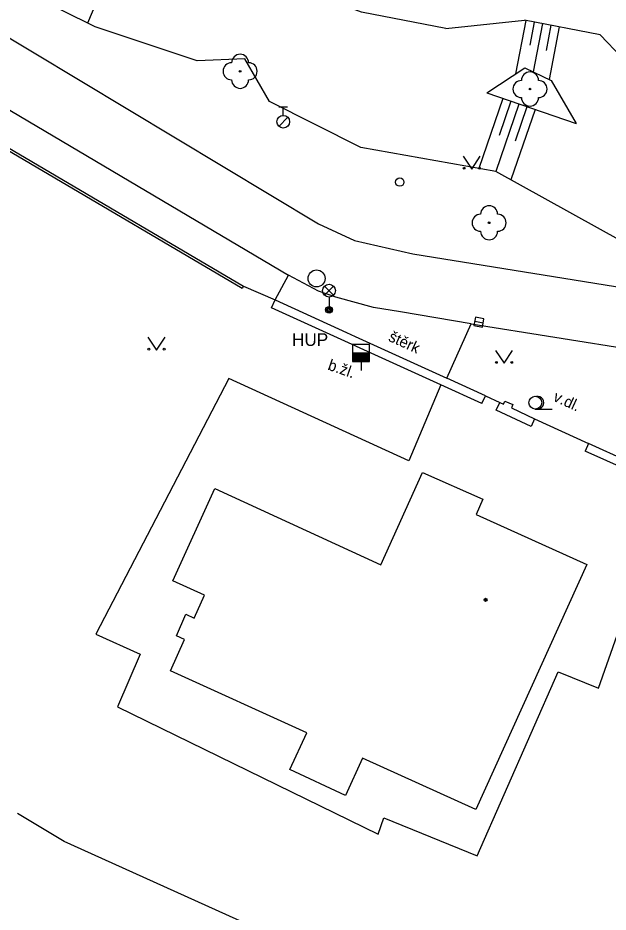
# Model space of a CAD drawing. Extents: x -600309 to -598967, y -1161267 to -1160292.
# Drawn here: x -600215.3 to -600180.6, y -1160958.5 to -1160906.1 of the extents above; entities that cross this region are included whole.
import ezdxf

# ---------------------------------------------------------------- set-up
doc = ezdxf.new("R2010")
doc.units = 0
for name, color, linetype in [('Level 10', 7, 'Continuous'), ('Level 11', 7, 'Continuous'), ('Level 14', 7, 'Continuous'), ('Level 15', 7, 'Continuous'), ('Level 22', 7, 'Continuous'), ('Level 27', 7, 'Continuous'), ('Level 28', 7, 'Continuous'), ('Level 33', 7, 'Continuous'), ('Level 36', 7, 'Continuous'), ('Level 39', 7, 'Continuous'), ('Level 40', 7, 'Continuous'), ('Level 41', 7, 'Continuous'), ('Level 5', 7, 'Continuous'), ('Level 7', 7, 'Continuous'), ('Level 8', 7, 'Continuous')]:
    doc.layers.add(name, color=color, linetype=linetype)

msp = doc.modelspace()

# ---------------------------------------------------------------- linework, layer by layer
at = {"layer": 'Level 10'}
for points in [[(-600225.66, -1160901.31), (-600197.65, -1160918.15)], [(-600228.03, -1160904.23), (-600199.41, -1160921.16)], [(-600197.65, -1160918.15), (-600195.53, -1160919.13), (-600192.11, -1160919.92)], [(-600192.11, -1160919.92), (-600173.16, -1160922.97)], [(-600192.83, -1160923.32), (-600194.41, -1160923.06), (-600196.64, -1160922.45), (-600197.65, -1160922.1), (-600199.41, -1160921.16)], [(-600188.68, -1160924.02), (-600192.83, -1160923.32)], [(-600188.68, -1160924.02), (-600173.95, -1160926.36)]]:
    msp.add_lwpolyline(points, dxfattribs=at)
at = {"layer": 'Level 11'}
for points in [[(-600200.2, -1160922.62), (-600199.41, -1160921.16)], [(-600190.11, -1160927.21), (-600188.68, -1160924.02)], [(-600190.46, -1160927.61), (-600192.34, -1160932.07), (-600202.92, -1160927.24), (-600210.73, -1160942.23), (-600208.11, -1160943.42), (-600209.46, -1160946.51), (-600194.14, -1160953.97), (-600193.82, -1160953.02), (-600188.34, -1160955.24), (-600183.58, -1160944.45), (-600181.2, -1160945.4), (-600177.07, -1160933.69)], [(-600212.58, -1160954.4), (-600215.33, -1160952.76)], [(-600186.92, -1160965.99), (-600212.58, -1160954.4)]]:
    msp.add_lwpolyline(points, dxfattribs=at)
at = {"layer": 'Level 14'}
for points in [[(-600190.17, -1160906.69), (-600195.12, -1160905.73), (-600208.06, -1160900.94), (-600213.45, -1160898.65), (-600216.15, -1160895.97), (-600217.64, -1160891.64), (-600217.72, -1160887.06), (-600215.26, -1160881.33)], [(-600168.15, -1160921.43), (-600172.65, -1160921.15), (-600178.38, -1160920), (-600187.23, -1160915.08), (-600195.17, -1160913.67), (-600200.53, -1160910.97), (-600201.98, -1160908.47), (-600204.78, -1160908.58), (-600210.76, -1160906.6), (-600216.52, -1160903.74), (-600221.25, -1160901.29), (-600224.94, -1160898.51), (-600225.28, -1160895)], [(-600163.59, -1160905.38), (-600166.17, -1160907.35), (-600168.53, -1160909.45), (-600170.75, -1160909.46), (-600174.94, -1160910.63), (-600178.56, -1160909.73), (-600181.12, -1160907.05), (-600185.56, -1160906.2)], [(-600190.17, -1160906.69), (-600185.56, -1160906.2)], [(-600187.77, -1160910.47), (-600185.53, -1160908.99), (-600183.99, -1160909.74), (-600182.52, -1160912.27)], [(-600187.77, -1160910.47), (-600182.52, -1160912.27)]]:
    msp.add_lwpolyline(points, dxfattribs=at)
at = {"layer": 'Level 15'}
for points in [[(-600208.78, -1160900.63), (-600211.22, -1160906.37)], [(-600185.48, -1160906.22), (-600186.08, -1160909.35)], [(-600184.99, -1160906.31), (-600185.24, -1160907.66)], [(-600184.49, -1160906.4), (-600185.04, -1160909.23)], [(-600184, -1160906.5), (-600184.29, -1160907.98)], [(-600183.51, -1160906.59), (-600184.1, -1160909.68)], [(-600186.82, -1160910.79), (-600188.23, -1160914.9)], [(-600186.35, -1160910.96), (-600187.04, -1160912.97)], [(-600185.88, -1160911.12), (-600187.24, -1160915.08)], [(-600184.93, -1160911.44), (-600186.35, -1160915.57)], [(-600185.41, -1160911.28), (-600186.1, -1160913.3)]]:
    msp.add_lwpolyline(points, dxfattribs=at)
at = {"layer": 'Level 22'}
for centre in [(-600202.25, -1160909.2), (-600185.23, -1160910.24), (-600187.63, -1160918.09)]:
    msp.add_circle(centre, 0.05, dxfattribs=at)
for centre, start, end in [((-600202.25, -1160908.7), 0, 180), ((-600202.75, -1160909.2), 90, 270), ((-600201.75, -1160909.2), 270, 90), ((-600185.23, -1160909.74), 0, 180), ((-600202.25, -1160909.7), 180, 0), ((-600185.73, -1160910.24), 90, 270), ((-600184.73, -1160910.24), 270, 90), ((-600185.23, -1160910.74), 180, 0), ((-600187.63, -1160917.59), 0, 180), ((-600188.13, -1160918.09), 90, 270), ((-600187.13, -1160918.09), 270, 90), ((-600187.63, -1160918.59), 180, 0)]:
    msp.add_arc(centre, 0.5, start, end, dxfattribs=at)
at = {"layer": 'Level 27'}
msp.add_line((-600188.4759, -1160923.875), (-600187.9841, -1160923.965), dxfattribs=at)
msp.add_lwpolyline([(-600188.5209, -1160924.121), (-600188.029, -1160924.2109), (-600187.9391, -1160923.719), (-600188.431, -1160923.6291)], close=True, dxfattribs=at)
msp.add_circle((-600197.76, -1160921.36), 0.5, dxfattribs=at)
at = {"layer": 'Level 28'}
for p, q in [((-600199.9699, -1160911.2849), (-600199.4699, -1160911.2849)), ((-600199.7199, -1160911.7849), (-600199.7199, -1160911.2849)), ((-600199.9779, -1160912.4319), (-600199.4479, -1160911.9019)), ((-600195.65, -1160925.73), (-600194.65, -1160925.73)), ((-600195.65, -1160925.78), (-600194.65, -1160925.78)), ((-600195.65, -1160925.83), (-600194.65, -1160925.83)), ((-600195.65, -1160925.88), (-600194.65, -1160925.88)), ((-600195.65, -1160925.93), (-600194.65, -1160925.93)), ((-600195.65, -1160925.98), (-600194.65, -1160925.98)), ((-600195.65, -1160926.03), (-600194.65, -1160926.03)), ((-600195.65, -1160926.08), (-600194.65, -1160926.08)), ((-600195.65, -1160926.13), (-600194.65, -1160926.13)), ((-600195.65, -1160926.18), (-600194.65, -1160926.18)), ((-600195.15, -1160926.23), (-600195.15, -1160926.76))]:
    msp.add_line(p, q, dxfattribs=at)
msp.add_lwpolyline([(-600195.65, -1160926.23), (-600194.65, -1160926.23), (-600194.65, -1160925.23), (-600195.65, -1160925.23)], close=True, dxfattribs=at)
for centre, radius in [((-600199.7199, -1160912.1599), 0.375), ((-600192.88, -1160915.7), 0.25)]:
    msp.add_circle(centre, radius, dxfattribs=at)
at = {"layer": 'Level 33'}
for p, q in [((-600197.295, -1160922.34), (-600196.765, -1160921.81)), ((-600197.295, -1160921.81), (-600196.765, -1160922.34)), ((-600197.03, -1160922.45), (-600197.03, -1160923.2))]:
    msp.add_line(p, q, dxfattribs=at)
for centre, radius in [((-600197.03, -1160922.075), 0.375), ((-600197.03, -1160923.2), 0.2), ((-600197.03, -1160923.2), 0.1445), ((-600197.03, -1160923.2), 0.0876)]:
    msp.add_circle(centre, radius, dxfattribs=at)
at = {"layer": 'Level 36'}
msp.add_line((-600184.92, -1160929.025), (-600183.92, -1160929.025), dxfattribs=at)
for points in [[(-600189.15, -1160914.19), (-600188.65, -1160914.94), (-600188.15, -1160914.19)], [(-600207.6599, -1160924.81), (-600207.1599, -1160925.56), (-600206.6599, -1160924.81)], [(-600187.25, -1160925.59), (-600186.75, -1160926.34), (-600186.25, -1160925.59)]]:
    msp.add_lwpolyline(points, dxfattribs=at)
for centre, radius in [((-600189.1002, -1160914.8898), 0.05), ((-600188.2008, -1160914.8898), 0.05), ((-600207.6101, -1160925.5098), 0.05), ((-600206.7107, -1160925.5098), 0.05), ((-600187.2002, -1160926.2898), 0.05), ((-600186.3008, -1160926.2898), 0.05), ((-600184.92, -1160928.6496), 0.375)]:
    msp.add_circle(centre, radius, dxfattribs=at)
msp.add_arc((-600184.795, -1160928.6496), 0.375, 260.40593, 99.59407, dxfattribs=at)
at = {"layer": 'Level 39'}
for radius in [0.09, 0.0398]:
    msp.add_circle((-600187.84, -1160940.2199), radius, dxfattribs=at)
at = {"layer": 'Level 5'}
for points in [[(-600193.99, -1160938.1599), (-600191.54, -1160932.75)], [(-600191.54, -1160932.75), (-600188, -1160934.32)], [(-600206.21, -1160939.1), (-600203.74, -1160933.68)], [(-600203.74, -1160933.68), (-600193.99, -1160938.1599)], [(-600188, -1160934.32), (-600188.39, -1160935.21)], [(-600188.39, -1160935.21), (-600181.9, -1160938.15)], [(-600181.9, -1160938.15), (-600188.42, -1160952.53)], [(-600204.35, -1160939.95), (-600206.21, -1160939.1)], [(-600204.95, -1160941.29), (-600204.35, -1160939.95)], [(-600205.99, -1160942.33), (-600205.44, -1160941.07)], [(-600205.44, -1160941.07), (-600204.95, -1160941.29)], [(-600205.51, -1160942.54), (-600205.99, -1160942.33)], [(-600206.33, -1160944.38), (-600205.51, -1160942.54)], [(-600198.34, -1160948.02), (-600206.33, -1160944.38)], [(-600199.33, -1160950.18), (-600198.34, -1160948.02)], [(-600195.06, -1160949.51), (-600196.06, -1160951.7)], [(-600188.42, -1160952.53), (-600195.06, -1160949.51)], [(-600196.06, -1160951.7), (-600199.33, -1160950.18)]]:
    msp.add_lwpolyline(points, dxfattribs=at)
at = {"layer": 'Level 7'}
for points in [[(-600202.13, -1160921.95), (-600227, -1160907.31)], [(-600226.92, -1160907.18), (-600202.05, -1160921.82), (-600202.13, -1160921.95)], [(-600200.41, -1160923.08), (-600200.2, -1160922.62), (-600196, -1160924.53)], [(-600188.06, -1160928.7), (-600190.46, -1160927.61), (-600200.41, -1160923.08)], [(-600196, -1160924.53), (-600195.49, -1160924.76), (-600190.11, -1160927.21)], [(-600187.85, -1160928.25), (-600190.11, -1160927.21)], [(-600188.06, -1160928.7), (-600187.85, -1160928.25)], [(-600187.21, -1160929.08), (-600187, -1160928.63)], [(-600187, -1160928.63), (-600186.79, -1160928.73)], [(-600186.79, -1160928.73), (-600186.71, -1160928.56), (-600186.23, -1160928.76), (-600186.32, -1160928.95)], [(-600185.17, -1160930.04), (-600187.21, -1160929.08)], [(-600186.32, -1160928.95), (-600184.96, -1160929.59)], [(-600184.96, -1160929.59), (-600185.17, -1160930.04)], [(-600181.79, -1160931.04), (-600182, -1160931.49)], [(-600177.14, -1160933.16), (-600181.79, -1160931.04)], [(-600172.7, -1160935.65), (-600177.07, -1160933.69), (-600182, -1160931.49)]]:
    msp.add_lwpolyline(points, dxfattribs=at)
at = {"layer": 'Level 8'}
for points in [[(-600202.05, -1160921.82), (-600200.2, -1160922.62)], [(-600187.85, -1160928.25), (-600187, -1160928.63)], [(-600184.96, -1160929.59), (-600181.79, -1160931.04)]]:
    msp.add_lwpolyline(points, dxfattribs=at)

# ---------------------------------------------------------------- texts
at = {"layer": 'Level 40'}
for s, rotation, p in [('štěrk', 335.51595, (-600193.59, -1160925)), ('b.žl.', 340.83288, (-600197.15, -1160926.7)), ('v.dl.', 335.42004, (-600183.92, -1160928.52))]:
    msp.add_text(s, height=0.65, rotation=rotation, dxfattribs=at).set_placement(p)
at = {"layer": 'Level 41'}
msp.add_text('HUP', height=0.75, dxfattribs=at).set_placement((-600199.2, -1160925.32))

doc.saveas('drawing.dxf')
